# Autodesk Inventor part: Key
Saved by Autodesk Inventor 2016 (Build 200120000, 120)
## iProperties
Created: 2018-02
Part Number: Key
Material: Generic
Document SubType Name: Modeling
Designer: Administrator
Appearance: Generic
Title: Key v4
Author: Administrator
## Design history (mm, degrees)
feature "Body2"
feature "Body3"
body "Solid1"
body "Solid2"
